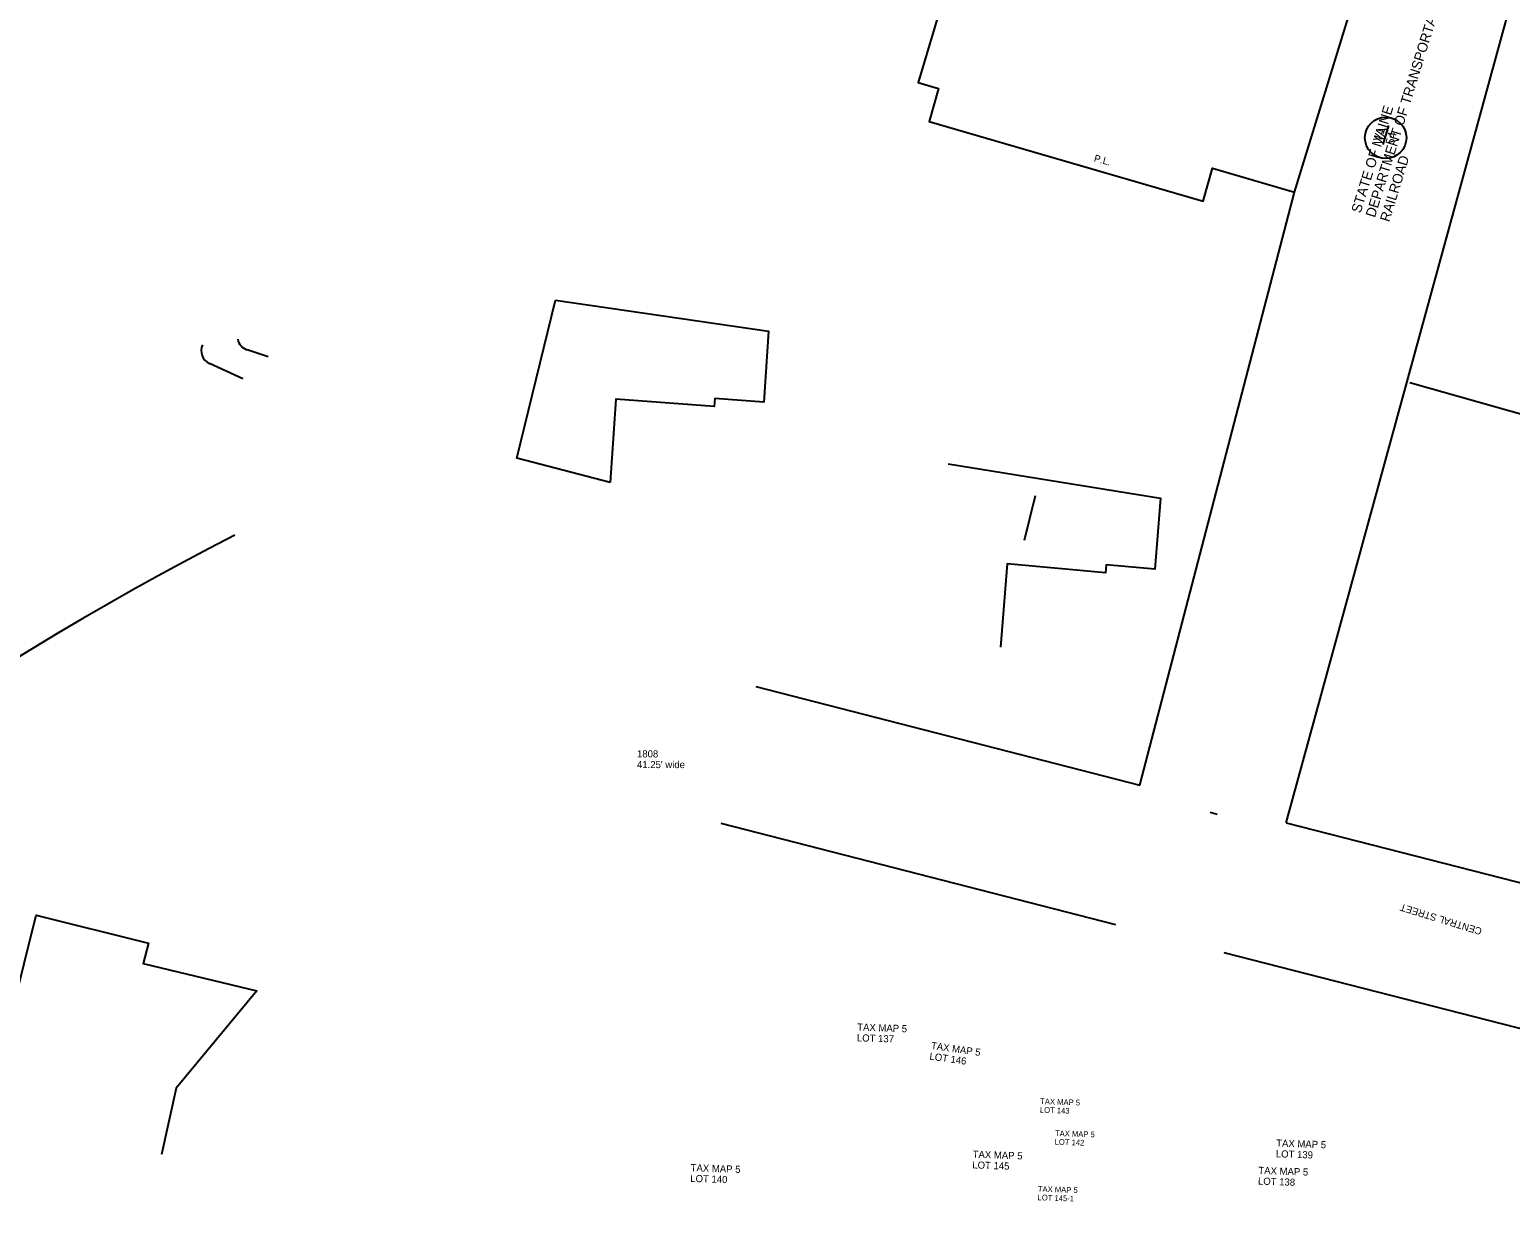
# Model space of a CAD drawing. Extents: x 1133267 to 1139526, y 528613 to 531538.
# Drawn here: x 1136530 to 1137049, y 530006 to 530418 of the extents above; entities that cross this region are included whole.
import ezdxf

# ---------------------------------------------------------------- set-up
doc = ezdxf.new("R2010")
doc.units = 0
for name, color, linetype in [('E_Property_Line', 7, 'Continuous'), ('E_ROW_Line', 7, 'Continuous'), ('E_ROW_Railroad', 7, 'Continuous'), ('E_ROW_TieLine', 7, 'Continuous'), ('MISCELLN TEXT', 7, 'Continuous'), ('PROPERTY NOTES', 7, 'Continuous'), ('PRP OWNER NAMES', 7, 'Continuous'), ('ROW REFERENCES', 7, 'Continuous'), ('TEMP RIGHTS', 7, 'Continuous')]:
    doc.layers.add(name, color=color, linetype=linetype)

msp = doc.modelspace()

# ---------------------------------------------------------------- linework, layer by layer
at = {"layer": 'E_Property_Line'}
msp.add_line((1137158.26, 530253.67), (1137013.97, 530294.65), dxfattribs=at)
msp.add_lwpolyline([(1136896.45, 530583.84), (1136841.53, 530399.91), (1136848.68, 530397.83), (1136845.43, 530386.27), (1136941.45, 530358.33), (1136944.69, 530369.88), (1136973.5, 530361.5)], dxfattribs=at)
at = {"layer": 'E_ROW_Line'}
for p, q in [((1136784.66, 530188.25), (1136919.3, 530153.69)), ((1136772.35, 530140.3), (1136910.75, 530104.78)), ((1136970.63, 530140.51), (1137116.59, 530103.05)), ((1136948.68, 530095.04), (1137103.39, 530055.33))]:
    msp.add_line(p, q, dxfattribs=at)
at = {"layer": 'E_ROW_Railroad'}
for p, q in [((1136973.5, 530361.5), (1137016.94, 530502.89)), ((1136970.63, 530140.51), (1137048.18, 530423.41)), ((1136919.3, 530153.69), (1136973.5, 530361.5))]:
    msp.add_line(p, q, dxfattribs=at)
at = {"layer": 'E_ROW_TieLine'}
for p, q in [((1137004.62, 530378.17), (1137006.6, 530384.91)), ((1136613.77, 530303.81), (1136606.34, 530306.27)), ((1136604.8, 530296.07), (1136593.16, 530301.4)), ((1136878.84, 530239.57), (1136882.74, 530255.15)), ((1136946.33, 530143.43), (1136943.92, 530144.1))]:
    msp.add_line(p, q, dxfattribs=at)
for points in [[(1136852.13, 530266.24), (1136926.57, 530254.22), (1136924.57, 530229.4), (1136907.44, 530230.93), (1136907.19, 530228.14), (1136872.73, 530231.21), (1136870.38, 530202)], [(1136515.45, 530040.3), (1136532.44, 530108.1), (1136571.72, 530098.24), (1136569.87, 530091.18), (1136609.73, 530081.54), (1136581.46, 530047.43), (1136576.29, 530024.2)]]:
    msp.add_lwpolyline(points, dxfattribs=at)
msp.add_circle((1137005.45, 530380.55), 7.26, dxfattribs=at)
for centre, radius, start, end in [((1136595.25, 530305.95), 5, 155.3639, 245.3639), ((1136607.91, 530311.01), 5, 192.2665, 251.7025), ((1137113, 529244.92), 1119.71, 117.14906, 150.19906)]:
    msp.add_arc(centre, radius, start, end, dxfattribs=at)
at = {"layer": 'TEMP RIGHTS'}
for points in [[(1136733.66, 530259.7), (1136700.86, 530268.25), (1136714.47, 530323.66)], [(1136714.47, 530323.66), (1136789.08, 530312.74), (1136787.44, 530287.9), (1136770.29, 530289.17), (1136770.09, 530286.38), (1136735.58, 530288.94), (1136733.66, 530259.7)]]:
    msp.add_lwpolyline(points, dxfattribs=at)

# ---------------------------------------------------------------- texts
at = {"layer": 'E_Property_Line'}
msp.add_text('P.L.', height=2.5, rotation=345.3791, dxfattribs=at).set_placement((1136903.01, 530372.3))
at = {"layer": 'MISCELLN TEXT'}
for s, p in [('1808', (1136743.01, 530163.38)), ("41.25' wide", (1136743.01, 530159.63))]:
    msp.add_text(s, height=2.5, dxfattribs=at).set_placement(p)
msp.add_text('CENTRAL STREET', height=2.5, rotation=162.9782, dxfattribs=at).set_placement((1137039.4, 530103.46))
at = {"layer": 'PROPERTY NOTES'}
for s, height, rotation, p in [('TAX MAP 5', 2.5, 357.9281, (1136820.18, 530067.67)), ('LOT 137', 2.5, 357.9281, (1136820.05, 530063.92)), ('LOT 146', 2.5, 351.8395, (1136845.42, 530057.51)), ('TAX MAP 5', 2.5, 351.8395, (1136845.96, 530061.22)), ('TAX MAP 5', 2, 357.9281, (1136884.32, 530041.9)), ('LOT 143', 2, 357.9281, (1136884.21, 530038.88)), ('LOT 142', 2, 357.9281, (1136889.39, 530027.7)), ('TAX MAP 5', 2, 357.9281, (1136889.5, 530030.72)), ('TAX MAP 5', 2.5, 357.9281, (1136967.05, 530027.02)), ('TAX MAP 5', 2.5, 357.9281, (1136860.65, 530023.1)), ('LOT 139', 2.5, 357.9281, (1136966.92, 530023.27)), ('TAX MAP 5', 2.5, 357.9281, (1136761.79, 530018.38)), ('LOT 145', 2.5, 357.9281, (1136860.52, 530019.36)), ('TAX MAP 5', 2.5, 357.9281, (1136960.8, 530017.44)), ('LOT 140', 2.5, 357.9281, (1136761.65, 530014.63)), ('TAX MAP 5', 2, 357.9281, (1136883.5, 530011.21)), ('LOT 138', 2.5, 357.9281, (1136960.66, 530013.7)), ('LOT 145-1', 2, 357.9281, (1136883.4, 530008.21))]:
    msp.add_text(s, height=height, rotation=rotation, dxfattribs=at).set_placement(p)
at = {"layer": 'PRP OWNER NAMES'}
for s, p in [('DEPARTMENT OF TRANSPORTATION', (1137001.68, 530352.4)), ('STATE OF MAINE', (1136996.67, 530353.95)), ('RAILROAD', (1137006.7, 530350.85))]:
    msp.add_text(s, height=3.5, rotation=72.8069, dxfattribs=at).set_placement(p)
at = {"layer": 'ROW REFERENCES'}
for s, rotation, p in [('V1', 73.763, (1137003.93, 530378.96)), ('54', 76.2184, (1137008.26, 530377.86))]:
    msp.add_text(s, height=3, rotation=rotation, dxfattribs=at).set_placement(p)

doc.saveas('drawing.dxf')
